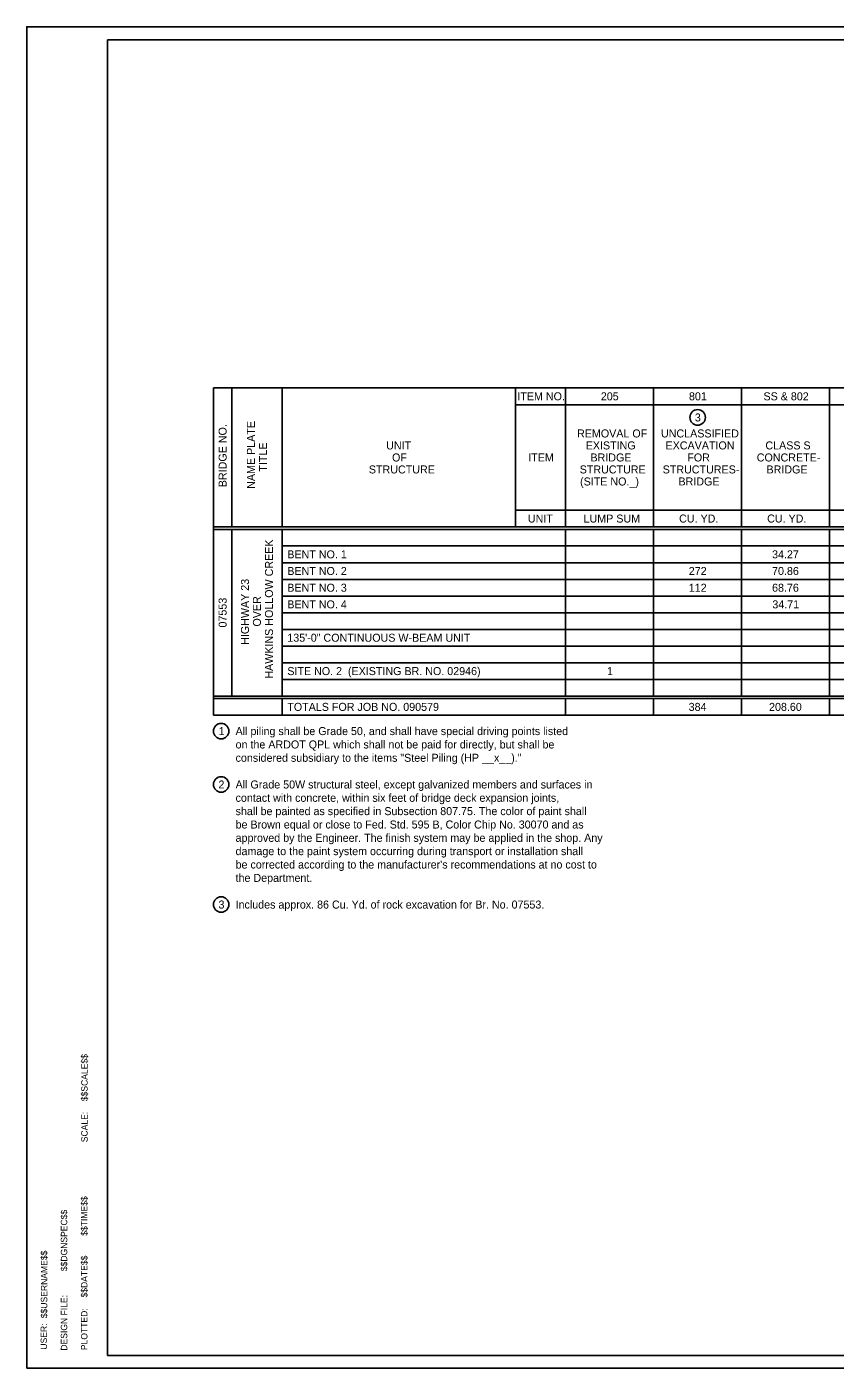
# Model space of a CAD drawing. Extents: x -1.3 to 32.1, y -0.4 to 20.7.
# Drawn here: x -1.26 to 11.36, y -0.2 to 20.75 of the extents above; entities that cross this region are included whole.
import ezdxf

# ---------------------------------------------------------------- set-up
doc = ezdxf.new("R2010")
doc.units = 0
for name, color, linetype in [('Level 1', 7, 'Continuous'), ('Level 4', 7, 'Continuous'), ('Level 63', 7, 'Continuous')]:
    doc.layers.add(name, color=color, linetype=linetype)

msp = doc.modelspace()

# ---------------------------------------------------------------- linework, layer by layer
at = {"layer": 'Level 1'}
for p, q in [((-0.001, 20.545), (31.617, 20.545)), ((-0.001, -0.001), (-0.001, 20.545)), ((31.617, -0.001), (-0.001, -0.001))]:
    msp.add_line(p, q, dxfattribs=at)
at = {"layer": 'Level 4'}
for p, q in [((29.152, 15.107), (1.652, 15.107)), ((1.652, 15.107), (1.652, 9.996)), ((1.939, 15.107), (1.939, 12.937)), ((2.725, 15.107), (2.725, 12.937)), ((6.369, 15.107), (6.369, 12.937)), ((7.152, 15.107), (7.152, 12.937)), ((7.152, 15.107), (7.152, 12.937)), ((8.527, 15.107), (8.527, 12.937)), ((9.902, 15.107), (9.902, 12.937)), ((9.902, 15.107), (9.902, 12.937)), ((11.277, 15.107), (11.277, 12.937)), ((29.152, 14.846), (6.369, 14.846)), ((29.152, 13.198), (6.369, 13.198)), ((29.152, 12.937), (1.652, 12.937)), ((29.152, 12.899), (1.652, 12.899)), ((1.939, 12.899), (1.939, 10.295)), ((2.725, 12.899), (2.725, 10.295)), ((7.152, 12.899), (7.152, 10.295)), ((7.152, 12.899), (7.152, 10.295)), ((8.527, 12.899), (8.527, 10.295)), ((9.902, 12.899), (9.902, 10.295)), ((9.902, 12.899), (9.902, 10.295)), ((11.277, 12.899), (11.277, 10.295)), ((29.152, 12.639), (2.725, 12.639)), ((29.152, 12.378), (2.725, 12.378)), ((29.152, 12.118), (2.725, 12.118)), ((29.152, 11.857), (2.725, 11.857)), ((29.152, 11.857), (2.725, 11.857)), ((29.152, 11.597), (2.725, 11.597)), ((29.152, 11.337), (2.725, 11.337)), ((29.152, 11.076), (2.725, 11.076)), ((29.152, 10.816), (2.725, 10.816)), ((29.152, 10.555), (2.725, 10.555)), ((29.152, 10.295), (1.652, 10.295)), ((29.152, 10.257), (1.652, 10.257)), ((2.725, 10.257), (2.725, 9.996)), ((7.152, 10.257), (7.152, 9.996)), ((7.152, 10.257), (7.152, 9.996)), ((8.527, 10.257), (8.527, 9.996)), ((9.902, 10.257), (9.902, 9.996)), ((9.902, 10.257), (9.902, 9.996)), ((11.277, 10.257), (11.277, 9.996)), ((29.152, 9.996), (1.652, 9.996)), ((-0.001, -0.001), (-0.001, 6.284)), ((19.866, -0.001), (-0.001, -0.001))]:
    msp.add_line(p, q, dxfattribs=at)
for centre in [(9.215, 14.647), (1.773, 9.748), (1.773, 8.915), (1.773, 7.04)]:
    msp.add_circle(centre, 0.121, dxfattribs=at)
at = {"layer": 'Level 63'}
msp.add_lwpolyline([(-1.263, -0.201), (32.067, -0.201), (32.067, 20.747), (-1.263, 20.747)], close=True, dxfattribs=at)

# ---------------------------------------------------------------- texts
at = {"layer": 'Level 1'}
for s, p in [('$$SCALE$$', (-0.313, 3.969)), ('SCALE:', (-0.313, 3.328)), ('$$TIME$$', (-0.316, 1.867)), ('$$DGNSPEC$$', (-0.632, 1.314)), ('$$USERNAME$$', (-0.944, 0.58)), ('$$DATE$$', (-0.316, 0.903)), ('DESIGN FILE:', (-0.632, 0.073)), ('PLOTTED:', (-0.316, 0.081)), ('USER:', (-0.948, 0.089))]:
    msp.add_text(s, height=0.1, rotation=90, dxfattribs=at).set_placement(p)
at = {"layer": 'Level 4'}
for s, p in [('ITEM NO.', (6.399, 14.914)), ('205', (7.703, 14.914)), ('801', (9.08, 14.914)), ('SS & 802', (10.244, 14.914)), ('3', (9.172, 14.584)), ('REMOVAL OF', (7.332, 14.334)), ('UNCLASSIFIED', (8.643, 14.334)), ('UNIT', (4.35, 14.147)), ('EXISTING', (7.467, 14.147)), ('EXCAVATION', (8.714, 14.147)), ('CLASS S', (10.274, 14.147)), ('OF', (4.442, 13.959)), ('ITEM', (6.569, 13.959)), ('BRIDGE', (7.541, 13.959)), ('FOR', (9.054, 13.959)), ('CONCRETE-', (10.139, 13.959)), ('STRUCTURE', (4.08, 13.772)), ('STRUCTURE', (7.373, 13.772)), ('STRUCTURES-', (8.669, 13.772)), ('BRIDGE', (10.291, 13.772)), ('(SITE NO._)', (7.379, 13.584)), ('BRIDGE', (8.916, 13.584)), ('UNIT', (6.564, 13.005)), ('LUMP SUM', (7.434, 13.005)), ('CU. YD.', (8.926, 13.005)), ('CU. YD.', (10.301, 13.005)), ('BENT NO. 1', (2.806, 12.446)), ('34.27', (10.378, 12.446)), ('BENT NO. 2', (2.806, 12.186)), ('272', (9.077, 12.186)), ('70.86', (10.378, 12.186)), ('BENT NO. 3', (2.806, 11.925)), ('112', (9.077, 11.925)), ('68.76', (10.378, 11.925)), ('BENT NO. 4', (2.806, 11.665)), ('34.71', (10.382, 11.665)), ('135\'-0" CONTINUOUS W-BEAM UNIT', (2.806, 11.144)), ('SITE NO. 2  (EXISTING BR. NO. 02946)', (2.806, 10.623)), ('1', (7.8, 10.623)), ('TOTALS FOR JOB NO. 090579', (2.806, 10.064)), ('384', (9.075, 10.064)), ('208.60', (10.331, 10.064)), ('1', (1.733, 9.686)), ('All piling shall be Grade 50, and shall have special driving points listed', (1.998, 9.686)), ('on the ARDOT QPL which shall not be paid for directly, but shall be ', (1.998, 9.477)), ('considered subsidiary to the items "Steel Piling (HP __x__)."', (1.998, 9.269)), ('2', (1.73, 8.852)), ('All Grade 50W structural steel, except galvanized members and surfaces in', (1.998, 8.852)), ('contact with concrete, within six feet of bridge deck expansion joints,', (1.998, 8.644)), ('shall be painted as specified in Subsection 807.75. The color of paint shall', (1.998, 8.436)), ('be Brown equal or close to Fed. Std. 595 B, Color Chip No. 30070 and as', (1.998, 8.227)), ('approved by the Engineer. The finish system may be applied in the shop. Any', (1.998, 8.019)), ('damage to the paint system occurring during transport or installation shall', (1.998, 7.811)), ("be corrected according to the manufacturer's recommendations at no cost to", (1.998, 7.602)), ('the Department.', (1.998, 7.394)), ('3', (1.731, 6.977)), ('Includes approx. 86 Cu. Yd. of rock excavation for Br. No. 07553.', (1.998, 6.977))]:
    msp.add_text(s, height=0.125, dxfattribs=at).set_placement(p)
for s, p in [('BRIDGE NO.', (1.858, 13.557)), ('NAME PLATE', (2.3, 13.532)), ('TITLE', (2.488, 13.8)), ('HAWKINS HOLLOW CREEK', (2.582, 10.567)), ('HIGHWAY 23', (2.207, 11.095)), ('07553', (1.858, 11.366)), ('OVER', (2.394, 11.381))]:
    msp.add_text(s, height=0.125, rotation=90, dxfattribs=at).set_placement(p)

doc.saveas('drawing.dxf')
